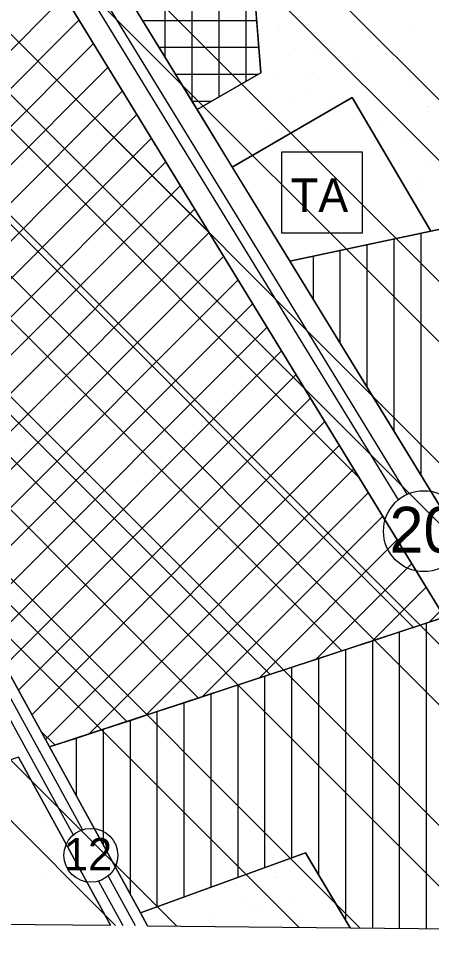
# Model space of a CAD drawing. Extents: x 409341 to 428634, y 4447481 to 4463281.
# Drawn here: x 420569 to 420722.5, y 4457778.3 to 4458119.5 of the extents above; entities that cross this region are included whole.
import ezdxf

# ---------------------------------------------------------------- set-up
doc = ezdxf.new("R2010")
doc.units = 0
for name, color, linetype in [('ADA', 7, 'Continuous'), ('ADAKENARI', 7, 'Continuous'), ('Default', 7, 'Continuous'), ('KALDIRIM', 7, 'Continuous'), ('KD_DAIRE', 7, 'Continuous'), ('KD_YGEN', 7, 'Continuous'), ('LJ_SEMBOL', 7, 'Continuous'), ('PL_AYA_PARK_DINLENME', 7, 'Continuous'), ('PL_K_AKARYAKIT_LPG_Y', 7, 'Continuous'), ('PL_K_K_D_K_C_A', 7, 'Continuous'), ('PL_KON_MEV_250', 7, 'Continuous'), ('PL_SAY_ORTAOGRETIM', 7, 'Continuous'), ('PL_TA_K_TA', 7, 'Continuous'), ('SN_TR_SIVILASMA', 7, 'Continuous'), ('TR_AKARYAKIT_SERVİS', 7, 'Continuous'), ('TR_KONUTDISIKCA', 7, 'Continuous'), ('TR_ORTAEGITIM', 7, 'Continuous'), ('TR_ORTAYOGUNKONUT', 7, 'Continuous'), ('TR_PARKALANI', 7, 'Continuous')]:
    doc.layers.add(name, color=color, linetype=linetype)

# ---------------------------------------------------------------- blocks, each defined once
blk = doc.blocks.new('POINT_DISPLAY')
at = {"layer": 'Default'}
blk.add_line((0, 0), (0, 0), dxfattribs=at)

msp = doc.modelspace()

# ---------------------------------------------------------------- linework, layer by layer
at = {"layer": 'ADA'}
for p, q in [((420652.94, 4458177.84), (420659.03, 4458099.33)), ((420635.42, 4458085.67), (420659.03, 4458099.33)), ((420648.47, 4458064.34), (420692.98, 4458090.1)), ((420692.98, 4458090.1), (420722.25, 4458040.54)), ((420795.15, 4458056.03), (420669.86, 4458029.4)), ((420614.35, 4457787.49), (420675.71, 4457809.73)), ((420675.71, 4457809.73), (420692.29, 4457781.9))]:
    msp.add_line(p, q, dxfattribs=at)
at = {"layer": 'ADAKENARI'}
for p, q in [((420491.4, 4458282.6), (420727.31, 4457897.27)), ((420576.48, 4458143.63), (420727.31, 4457897.27)), ((420669.71, 4458029.64), (420599.93, 4458143.63)), ((420822.23, 4457780.52), (420669.71, 4458029.64)), ((420580.61, 4457849.04), (420509.28, 4457979.16)), ((420580.61, 4457849.04), (420727.31, 4457897.27)), ((420614.35, 4457787.49), (420580.61, 4457849.04)), ((420569.02, 4457845.23), (420603.22, 4457782.84)), ((420616.98, 4457782.69), (420614.35, 4457787.49))]:
    msp.add_line(p, q, dxfattribs=at)
at = {"layer": 'KALDIRIM'}
for p, q in [((420585.86, 4458143.63), (420710.07, 4457940.74)), ((420662.89, 4458025.47), (420590.55, 4458143.63)), ((420713.47, 4457942.85), (420662.89, 4458025.47)), ((420502.26, 4457975.31), (420572.52, 4457847.15)), ((420577.1, 4457847.12), (420505.77, 4457977.24)), ((420576.03, 4457849.07), (420592.88, 4457818.33)), ((420572.52, 4457847.15), (420589.4, 4457816.37)), ((420602.32, 4457801.11), (420612.39, 4457782.74)), ((420598.79, 4457799.23), (420607.81, 4457782.79))]:
    msp.add_line(p, q, dxfattribs=at)
at = {"layer": 'KD_DAIRE'}
for centre, radius in [((420719.61, 4457929.16), 15), ((420595.96, 4457808.82), 10)]:
    msp.add_circle(centre, radius, dxfattribs=at)
at = {"layer": 'LJ_SEMBOL'}
msp.add_lwpolyline([(420666.8, 4458039.9), (420696.8, 4458039.9), (420696.8, 4458069.9), (420666.8, 4458069.9)], close=True, dxfattribs=at)
msp.add_lwpolyline([(420666.8, 4458039.9), (420696.8, 4458039.9), (420696.8, 4458069.9), (420666.8, 4458069.9)], close=True, dxfattribs=at)
at = {"layer": 'PL_AYA_PARK_DINLENME'}
for p, q in [((420652.94, 4458177.84), (420659.03, 4458099.33)), ((420659.03, 4458099.33), (420635.42, 4458085.67)), ((420648.47, 4458064.34), (420692.98, 4458090.1)), ((420692.98, 4458090.1), (420722.25, 4458040.54)), ((420635.42, 4458085.67), (420648.47, 4458064.34)), ((420722.25, 4458040.54), (420795.15, 4458056.03)), ((420616.98, 4457782.69), (420692.29, 4457781.9))]:
    msp.add_line(p, q, dxfattribs=at)
msp.add_lwpolyline([(420692.29, 4457781.9), (420675.71, 4457809.73), (420614.35, 4457787.49), (420616.98, 4457782.69)], dxfattribs=at)
at = {"layer": 'PL_K_AKARYAKIT_LPG_Y'}
msp.add_lwpolyline([(420616.54, 4458156.78), (420611.4, 4458153.8), (420606.54, 4458150.99), (420598.33, 4458146.24), (420599.93, 4458143.63), (420635.42, 4458085.67), (420659.03, 4458099.33), (420652.94, 4458177.84), (420646.54, 4458174.14), (420645.95, 4458173.8), (420636.54, 4458168.36), (420628.67, 4458163.8), (420626.54, 4458162.57), (420616.54, 4458156.78)], dxfattribs=at)
at = {"layer": 'PL_K_K_D_K_C_A'}
for points in [[(420720.61, 4457895.07), (420727.31, 4457897.27), (420576.48, 4458143.63), (420548.37, 4458189.54), (420546.29, 4458189.17), (420541.5, 4458188.3), (420531.5, 4458186.48), (420521.5, 4458184.66), (420511.5, 4458182.85), (420501.5, 4458181.03), (420491.5, 4458179.21), (420491.25, 4458179.17), (420481.5, 4458177.4), (420471.5, 4458175.58), (420461.5, 4458173.76), (420451.5, 4458171.95), (420441.5, 4458170.13), (420436.2, 4458169.17), (420445.81, 4458143.63), (420500.41, 4457998.46)], [(420509.28, 4457979.16), (420580.61, 4457849.04), (420590.61, 4457852.33), (420600.61, 4457855.61), (420610.61, 4457858.9), (420620.61, 4457862.19), (420630.61, 4457865.48), (420640.61, 4457868.77), (420650.61, 4457872.05), (420660.61, 4457875.34), (420670.61, 4457878.63), (420680.61, 4457881.92), (420690.61, 4457885.2), (420700.61, 4457888.49), (420710.61, 4457891.78), (420720.61, 4457895.07)]]:
    msp.add_lwpolyline(points, dxfattribs=at)
at = {"layer": 'PL_KON_MEV_250'}
for p, q in [((420669.86, 4458029.4), (420822.23, 4457780.52)), ((420692.29, 4457781.9), (420798.63, 4457780.77))]:
    msp.add_line(p, q, dxfattribs=at)
for points in [[(420823.57, 4458329.25), (420740.42, 4458310.37), (420744.27, 4458292.48), (420775.05, 4458149.45), (420795.15, 4458056.03), (420722.25, 4458040.54), (420669.86, 4458029.4)], [(420798.63, 4457780.77), (420727.31, 4457897.27), (420580.61, 4457849.04), (420614.35, 4457787.49), (420675.71, 4457809.73), (420692.29, 4457781.9)]]:
    msp.add_lwpolyline(points, dxfattribs=at)
at = {"layer": 'PL_SAY_ORTAOGRETIM'}
msp.add_line((420505.55, 4457783.87), (420603.22, 4457782.84), dxfattribs=at)
msp.add_lwpolyline([(420603.22, 4457782.84), (420569.02, 4457845.23), (420508.01, 4457825.17), (420505.55, 4457783.87)], dxfattribs=at)
at = {"layer": 'PL_TA_K_TA'}
for p, q in [((420692.98, 4458090.1), (420648.47, 4458064.34)), ((420722.25, 4458040.54), (420692.98, 4458090.1)), ((420648.47, 4458064.34), (420669.71, 4458029.64)), ((420669.86, 4458029.4), (420722.25, 4458040.54)), ((420669.71, 4458029.64), (420669.86, 4458029.4))]:
    msp.add_line(p, q, dxfattribs=at)
at = {"layer": 'SN_TR_SIVILASMA'}
for p, q in [((420809.31, 4457780.66), (420446.34, 4458143.63)), ((420832, 4457780.42), (420468.79, 4458143.63)), ((420877.38, 4457779.94), (420513.69, 4458143.63)), ((420900.07, 4457779.7), (420536.14, 4458143.63)), ((420945.45, 4457779.22), (420581.04, 4458143.63)), ((420968.14, 4457778.98), (420603.49, 4458143.63)), ((421013.52, 4457778.5), (420648.4, 4458143.63)), ((421036.21, 4457778.26), (420670.85, 4458143.63)), ((420763.93, 4457781.14), (420413.37, 4458131.7)), ((420741.24, 4457781.38), (420405.02, 4458117.6)), ((420695.85, 4457781.86), (420390.05, 4458087.66)), ((420673.16, 4457782.1), (420382.57, 4458072.7)), ((420627.78, 4457782.58), (420367.6, 4458042.76)), ((420605.09, 4457782.82), (420360.12, 4458027.79))]:
    msp.add_line(p, q, dxfattribs=at)
at = {"layer": 'TR_AKARYAKIT_SERVİS'}
for p, q in [((420653.59, 4458096.19), (420653.59, 4458169.48)), ((420623.59, 4458104.99), (420623.59, 4458125.78)), ((420633.59, 4458088.66), (420633.59, 4458125.78)), ((420643.59, 4458090.4), (420643.59, 4458125.78)), ((420615.14, 4458118.79), (420657.52, 4458118.79)), ((420621.26, 4458108.79), (420658.29, 4458108.79)), ((420627.39, 4458098.79), (420658.08, 4458098.79)), ((420633.51, 4458088.79), (420640.8, 4458088.79))]:
    msp.add_line(p, q, dxfattribs=at)
msp.add_lwpolyline([(420636.54, 4458168.36), (420628.67, 4458163.8), (420626.54, 4458162.57), (420616.54, 4458156.78), (420611.4, 4458153.8), (420606.54, 4458150.99), (420598.33, 4458146.24), (420599.93, 4458143.63), (420635.42, 4458085.67), (420659.03, 4458099.33), (420652.94, 4458177.84), (420646.54, 4458174.14), (420645.95, 4458173.8), (420636.54, 4458168.36)], dxfattribs=at)
at = {"layer": 'TR_KONUTDISIKCA'}
for p, q in [((420715.7, 4457893.45), (420465.52, 4458143.63)), ((420695.84, 4457948.66), (420500.88, 4458143.63)), ((420640.03, 4458039.83), (420536.23, 4458143.63)), ((420488.54, 4458030.02), (420586.23, 4458127.71)), ((420689.09, 4457884.7), (420455.24, 4458118.55)), ((420492.41, 4458019.74), (420591.6, 4458118.93)), ((420496.27, 4458009.46), (420596.97, 4458110.16)), ((420500.14, 4457999.19), (420602.34, 4458101.39)), ((420504.27, 4457989.17), (420607.71, 4458092.62)), ((420508.97, 4457979.73), (420613.08, 4458083.85)), ((420513.97, 4457970.6), (420618.45, 4458075.08)), ((420518.98, 4457961.46), (420623.82, 4458066.3)), ((420662.48, 4457875.96), (420476.55, 4458061.88)), ((420523.99, 4457952.33), (420629.19, 4458057.53)), ((420528.99, 4457943.19), (420634.56, 4458048.76)), ((420534, 4457934.06), (420639.93, 4458039.99)), ((420539.01, 4457924.92), (420645.3, 4458031.22)), ((420544.02, 4457915.79), (420650.67, 4458022.44)), ((420549.02, 4457906.65), (420656.04, 4458013.67)), ((420635.88, 4457867.21), (420497.87, 4458005.21)), ((420554.03, 4457897.52), (420661.41, 4458004.9)), ((420559.04, 4457888.39), (420666.78, 4457996.13)), ((420564.05, 4457879.25), (420672.15, 4457987.36)), ((420569.06, 4457870.12), (420677.52, 4457978.58)), ((420574.06, 4457860.98), (420682.89, 4457969.81)), ((420579.07, 4457851.85), (420688.26, 4457961.04)), ((420595.2, 4457853.84), (420693.63, 4457952.27)), ((420616.27, 4457860.76), (420699, 4457943.5)), ((420609.27, 4457858.46), (420534.4, 4457933.32)), ((420637.34, 4457867.69), (420704.38, 4457934.73)), ((420658.41, 4457874.62), (420709.75, 4457925.95)), ((420679.48, 4457881.54), (420715.12, 4457917.18)), ((420700.55, 4457888.47), (420720.49, 4457908.41)), ((420721.62, 4457895.4), (420725.86, 4457899.64)), ((420582.66, 4457849.71), (420577.31, 4457855.07))]:
    msp.add_line(p, q, dxfattribs=at)
at = {"layer": 'TR_ORTAYOGUNKONUT'}
for p, q in [((420718.59, 4457949.81), (420718.59, 4458039.76)), ((420708.59, 4457966.14), (420708.59, 4458037.63)), ((420688.59, 4457998.81), (420688.59, 4458033.38)), ((420698.59, 4457982.48), (420698.59, 4458035.51)), ((420678.59, 4458015.15), (420678.59, 4458031.25)), ((420720.61, 4457781.6), (420720.61, 4457895.07)), ((420710.61, 4457781.71), (420710.61, 4457891.78)), ((420710.61, 4457781.71), (420710.61, 4457891.78)), ((420700.61, 4457781.81), (420700.61, 4457888.49)), ((420700.61, 4457781.81), (420700.61, 4457888.49)), ((420690.61, 4457784.72), (420690.61, 4457885.2)), ((420690.61, 4457784.72), (420690.61, 4457885.2)), ((420670.61, 4457807.88), (420670.61, 4457878.63)), ((420680.61, 4457801.51), (420680.61, 4457881.92)), ((420680.61, 4457801.51), (420680.61, 4457881.92)), ((420660.61, 4457804.25), (420660.61, 4457875.34)), ((420650.61, 4457800.63), (420650.61, 4457872.05)), ((420640.61, 4457797.01), (420640.61, 4457868.77)), ((420630.61, 4457793.38), (420630.61, 4457865.48)), ((420620.61, 4457789.76), (420620.61, 4457862.19)), ((420610.61, 4457794.32), (420610.61, 4457858.9)), ((420600.61, 4457812.56), (420600.61, 4457855.61)), ((420590.61, 4457830.8), (420590.61, 4457852.33))]:
    msp.add_line(p, q, dxfattribs=at)
msp.add_lwpolyline([(420775.05, 4458149.45), (420795.15, 4458056.03), (420722.25, 4458040.54), (420669.86, 4458029.4), (420822.23, 4457780.52)], dxfattribs=at)

# ---------------------------------------------------------------- block references
at = {"layer": 'TR_ORTAEGITIM', "xscale": 0.1, "yscale": 0.10000000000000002}
for p in [(420579.92, 4457821.08), (420579.92, 4457801.08)]:
    msp.add_blockref('POINT_DISPLAY', p, dxfattribs=at)
at = {"layer": 'TR_PARKALANI', "xscale": 0.1, "yscale": 0.10000000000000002}
for p in [(420665.1, 4458117.39), (420665.1, 4458117.39), (420665.73, 4458114.91), (420716.08, 4458116.22), (420716.08, 4458116.22), (420686.53, 4458111.01), (420686.53, 4458111.01), (420701.3, 4458113.61), (420701.3, 4458113.61), (420671.76, 4458108.41), (420671.76, 4458108.41), (420679.64, 4458107.38), (420686.96, 4458107.53), (420694.41, 4458104.78), (420707.96, 4458104.64), (420707.96, 4458104.64), (420710.05, 4458107.1), (420693.19, 4458102.03), (420693.19, 4458102.03), (420711.3, 4458101.85), (420711.3, 4458101.85), (420675.47, 4458097.89), (420675.47, 4458097.89), (420678.42, 4458099.43), (420678.42, 4458099.43), (420663.65, 4458096.82), (420663.65, 4458096.82), (420714.62, 4458095.66), (420714.62, 4458095.66), (420661.39, 4458090.29), (420677.03, 4458092.61), (420685.08, 4458090.45), (420685.08, 4458090.45), (420699.85, 4458093.05), (420699.85, 4458093.05), (420670.31, 4458087.84), (420670.31, 4458087.84), (420655.54, 4458085.24), (420655.54, 4458085.24), (420706.51, 4458084.07), (420706.51, 4458084.07), (420721.28, 4458086.68), (420721.28, 4458086.68), (420721.35, 4458084.8), (420640.76, 4458082.63), (420640.76, 4458082.63), (420702.41, 4458081.33), (420705.71, 4458082.48), (420644.02, 4458078.12), (420666.57, 4458077.37), (420647.42, 4458073.65), (420647.42, 4458073.65), (420662.2, 4458076.26), (420662.2, 4458076.26), (420713.17, 4458075.09), (420713.17, 4458075.09), (420657.92, 4458070.59), (420719.83, 4458066.11), (420719.83, 4458066.11), (420717.01, 4458060.18), (420717.86, 4458055.14), (420664.47, 4457800.42), (420664.47, 4457800.42), (420665.32, 4457802.54), (420679.24, 4457803.02), (420679.24, 4457803.02), (420645.41, 4457796.76), (420649.7, 4457797.81), (420649.7, 4457797.81), (420653.83, 4457792.9), (420653.83, 4457792.9), (420671.13, 4457791.44), (420671.13, 4457791.44), (420656.36, 4457788.83), (420656.36, 4457788.83), (420659.31, 4457789.23), (420674.09, 4457786.62), (420626.82, 4457783.63), (420626.82, 4457783.63), (420641.59, 4457786.23), (420641.59, 4457786.23), (420677.79, 4457782.46), (420677.79, 4457782.46)]:
    msp.add_blockref('POINT_DISPLAY', p, dxfattribs=at)

# ---------------------------------------------------------------- texts
at = {"layer": 'KD_YGEN'}
for s, height, p in [('20', 17, (420706.84, 4457921.2)), ('12', 12, (420585.98, 4457803.2))]:
    msp.add_text(s, height=height, dxfattribs=at).set_placement(p)
at = {"layer": 'LJ_SEMBOL'}
msp.add_text('TA', height=12.5, dxfattribs=at).set_placement((420670.18, 4458047.59))
msp.add_text('TA', height=12.5, dxfattribs=at).set_placement((420670.18, 4458047.59))

doc.saveas('drawing.dxf')
